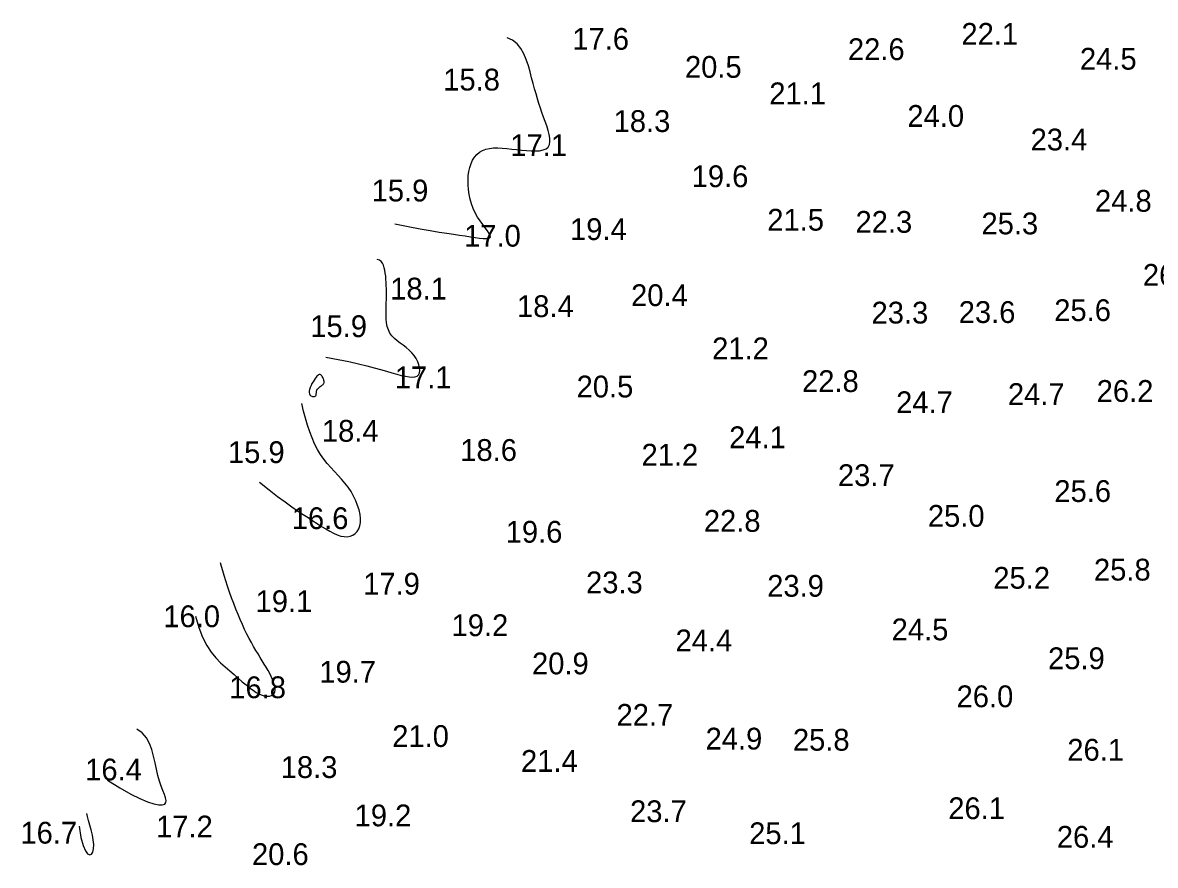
# Model space of a CAD drawing. Extents: x 3040093 to 3056816, y 408076 to 509144.
# Drawn here: x 3044183.2 to 3044443.1, y 433004.5 to 433197.9 of the extents above; entities that cross this region are included whole.
import ezdxf

# ---------------------------------------------------------------- set-up
doc = ezdxf.new("R2010")
doc.units = 0
doc.layers.add('V-CHAN-CONT-EL17', color=7, linetype='Continuous')
doc.layers.add('V-TOPO-SOUN-0610', color=7, linetype='Continuous')

msp = doc.modelspace()

# ---------------------------------------------------------------- linework, layer by layer
at = {"layer": 'V-CHAN-CONT-EL17'}
for points in [[(3044268.59, 433151.73), (3044271.68, 433151.1), (3044274.38, 433150.58), (3044276.72, 433150.17), (3044278.75, 433149.83), (3044280.53, 433149.56), (3044282.09, 433149.33), (3044283.48, 433149.13), (3044284.75, 433148.95), (3044285.94, 433148.77), (3044287.02, 433148.6), (3044288, 433148.46), (3044288.84, 433148.36), (3044289.54, 433148.32), (3044290.07, 433148.36), (3044290.42, 433148.48), (3044290.56, 433148.72), (3044290.5, 433149.08), (3044290.25, 433149.54), (3044289.86, 433150.12), (3044289.37, 433150.79), (3044288.8, 433151.55), (3044288.2, 433152.38), (3044287.61, 433153.29), (3044287.06, 433154.25), (3044286.59, 433155.26), (3044286.19, 433156.31), (3044285.88, 433157.39), (3044285.65, 433158.48), (3044285.49, 433159.58), (3044285.4, 433160.66), (3044285.4, 433161.73), (3044285.46, 433162.76), (3044285.6, 433163.74), (3044285.81, 433164.67), (3044286.1, 433165.54), (3044286.46, 433166.34), (3044286.91, 433167.05), (3044287.43, 433167.66), (3044288.04, 433168.18), (3044288.73, 433168.58), (3044289.5, 433168.86), (3044290.35, 433169.04), (3044291.26, 433169.13), (3044292.24, 433169.15), (3044293.26, 433169.1), (3044294.33, 433169.01), (3044295.43, 433168.89), (3044296.55, 433168.76), (3044297.69, 433168.63), (3044298.81, 433168.52), (3044299.9, 433168.45), (3044300.92, 433168.44), (3044301.84, 433168.51), (3044302.65, 433168.67), (3044303.31, 433168.94), (3044303.79, 433169.35), (3044304.08, 433169.9), (3044304.2, 433170.57), (3044304.17, 433171.36), (3044304.01, 433172.24), (3044303.77, 433173.18), (3044303.45, 433174.18), (3044303.1, 433175.21), (3044302.73, 433176.24), (3044302.37, 433177.27), (3044302.02, 433178.3), (3044301.68, 433179.35), (3044301.34, 433180.42), (3044301.01, 433181.53), (3044300.67, 433182.69), (3044300.34, 433183.92), (3044300, 433185.21), (3044299.64, 433186.59), (3044299.25, 433188), (3044298.78, 433189.4), (3044298.22, 433190.74), (3044297.53, 433191.96), (3044296.67, 433193.02), (3044295.62, 433193.86), (3044294.35, 433194.44)], [(3044252.8, 433121.1), (3044255.61, 433120.6), (3044258.08, 433120.1), (3044260.25, 433119.61), (3044262.17, 433119.15), (3044263.85, 433118.7), (3044265.34, 433118.28), (3044266.68, 433117.89), (3044267.9, 433117.53), (3044269.04, 433117.21), (3044270.08, 433116.94), (3044271.03, 433116.73), (3044271.88, 433116.6), (3044272.61, 433116.55), (3044273.22, 433116.61), (3044273.71, 433116.77), (3044274.06, 433117.07), (3044274.27, 433117.49), (3044274.35, 433118.03), (3044274.3, 433118.65), (3044274.14, 433119.33), (3044273.87, 433120.05), (3044273.49, 433120.78), (3044273.03, 433121.49), (3044272.48, 433122.15), (3044271.86, 433122.76), (3044271.19, 433123.31), (3044270.5, 433123.84), (3044269.8, 433124.35), (3044269.12, 433124.87), (3044268.49, 433125.41), (3044267.94, 433126), (3044267.47, 433126.65), (3044267.12, 433127.38), (3044266.87, 433128.18), (3044266.71, 433129.03), (3044266.62, 433129.91), (3044266.58, 433130.83), (3044266.58, 433131.74), (3044266.61, 433132.66), (3044266.64, 433133.55), (3044266.66, 433134.41), (3044266.67, 433135.24), (3044266.67, 433136.04), (3044266.66, 433136.81), (3044266.64, 433137.56), (3044266.61, 433138.29), (3044266.56, 433139), (3044266.5, 433139.7), (3044266.42, 433140.39), (3044266.32, 433141.05), (3044266.19, 433141.66), (3044266, 433142.22), (3044265.76, 433142.71), (3044265.45, 433143.1), (3044265.05, 433143.39), (3044264.57, 433143.55)], [(3044237.56, 433092.43), (3044239.75, 433090.67), (3044241.7, 433089.17), (3044243.42, 433087.89), (3044244.94, 433086.79), (3044246.3, 433085.85), (3044247.54, 433085.03), (3044248.68, 433084.29), (3044249.75, 433083.59), (3044250.78, 433082.92), (3044251.77, 433082.29), (3044252.73, 433081.69), (3044253.65, 433081.16), (3044254.54, 433080.7), (3044255.38, 433080.34), (3044256.19, 433080.07), (3044256.96, 433079.93), (3044257.68, 433079.92), (3044258.35, 433080.04), (3044258.96, 433080.28), (3044259.5, 433080.64), (3044259.96, 433081.12), (3044260.31, 433081.71), (3044260.57, 433082.4), (3044260.7, 433083.19), (3044260.71, 433084.08), (3044260.61, 433085.04), (3044260.39, 433086.06), (3044260.06, 433087.11), (3044259.64, 433088.18), (3044259.14, 433089.25), (3044258.55, 433090.29), (3044257.88, 433091.29), (3044257.16, 433092.23), (3044256.38, 433093.12), (3044255.57, 433094), (3044254.74, 433094.87), (3044253.91, 433095.77), (3044253.08, 433096.7), (3044252.29, 433097.69), (3044251.54, 433098.77), (3044250.84, 433099.95), (3044250.2, 433101.21), (3044249.61, 433102.57), (3044249.06, 433104.01), (3044248.55, 433105.53), (3044248.08, 433107.11), (3044247.64, 433108.75), (3044247.23, 433110.45)], [(3044222.83, 433061.7), (3044223.6, 433059.06), (3044224.46, 433056.84), (3044225.42, 433054.98), (3044226.44, 433053.43), (3044227.5, 433052.12), (3044228.58, 433051), (3044229.65, 433050.02), (3044230.7, 433049.12), (3044231.71, 433048.26), (3044232.67, 433047.42), (3044233.58, 433046.64), (3044234.46, 433045.91), (3044235.28, 433045.24), (3044236.07, 433044.66), (3044236.81, 433044.17), (3044237.51, 433043.79), (3044238.17, 433043.51), (3044238.79, 433043.34), (3044239.34, 433043.28), (3044239.84, 433043.31), (3044240.26, 433043.44), (3044240.61, 433043.65), (3044240.87, 433043.95), (3044241.04, 433044.32), (3044241.1, 433044.77), (3044241.08, 433045.28), (3044240.97, 433045.85), (3044240.79, 433046.46), (3044240.55, 433047.12), (3044240.24, 433047.8), (3044239.9, 433048.5), (3044239.51, 433049.22), (3044239.09, 433049.94), (3044238.65, 433050.68), (3044238.19, 433051.43), (3044237.71, 433052.2), (3044237.21, 433053), (3044236.7, 433053.83), (3044236.19, 433054.7), (3044235.67, 433055.61), (3044235.16, 433056.57), (3044234.64, 433057.58), (3044234.13, 433058.63), (3044233.62, 433059.73), (3044233.11, 433060.88), (3044232.61, 433062.07), (3044232.11, 433063.3), (3044231.62, 433064.58), (3044231.14, 433065.89), (3044230.67, 433067.22), (3044230.23, 433068.54), (3044229.81, 433069.81), (3044229.43, 433071.01), (3044229.1, 433072.12), (3044228.81, 433073.11), (3044228.59, 433073.94)], [(3044202.66, 433024.01), (3044205.52, 433022.25), (3044207.99, 433020.85), (3044210.1, 433019.8), (3044211.87, 433019.06), (3044213.3, 433018.6), (3044214.42, 433018.38), (3044215.24, 433018.38), (3044215.78, 433018.55), (3044216.06, 433018.88), (3044216.11, 433019.35), (3044215.99, 433019.97), (3044215.73, 433020.73), (3044215.38, 433021.63), (3044214.98, 433022.66), (3044214.56, 433023.83), (3044214.19, 433025.12), (3044213.87, 433026.54), (3044213.57, 433028.03), (3044213.25, 433029.55), (3044212.84, 433031.04), (3044212.31, 433032.46), (3044211.59, 433033.76), (3044210.63, 433034.87), (3044209.38, 433035.76)], [(3044196.12, 433013.45), (3044196.55, 433010.9), (3044197.05, 433009.04), (3044197.57, 433007.79), (3044198.09, 433007.1), (3044198.57, 433006.87), (3044198.99, 433007.05), (3044199.3, 433007.55), (3044199.48, 433008.31), (3044199.51, 433009.24), (3044199.4, 433010.31), (3044199.2, 433011.45), (3044198.93, 433012.61), (3044198.63, 433013.74), (3044198.33, 433014.78), (3044198.07, 433015.68), (3044197.88, 433016.4)]]:
    msp.add_lwpolyline(points, dxfattribs=at)
msp.add_lwpolyline([(3044250.07, 433115.86), (3044249.82, 433115.47), (3044249.59, 433115.04), (3044249.37, 433114.6), (3044249.18, 433114.16), (3044249.04, 433113.73), (3044248.96, 433113.33), (3044248.94, 433112.98), (3044249, 433112.69), (3044249.13, 433112.46), (3044249.31, 433112.28), (3044249.52, 433112.16), (3044249.74, 433112.08), (3044249.96, 433112.06), (3044250.16, 433112.08), (3044250.32, 433112.15), (3044250.44, 433112.25), (3044250.51, 433112.39), (3044250.55, 433112.56), (3044250.57, 433112.75), (3044250.59, 433112.95), (3044250.61, 433113.16), (3044250.65, 433113.37), (3044250.72, 433113.57), (3044250.83, 433113.76), (3044250.97, 433113.93), (3044251.13, 433114.1), (3044251.31, 433114.25), (3044251.5, 433114.39), (3044251.68, 433114.52), (3044251.85, 433114.64), (3044252.01, 433114.76), (3044252.13, 433114.86), (3044252.23, 433114.97), (3044252.3, 433115.08), (3044252.34, 433115.18), (3044252.37, 433115.3), (3044252.37, 433115.43), (3044252.35, 433115.57), (3044252.32, 433115.73), (3044252.27, 433115.9), (3044252.21, 433116.09), (3044252.14, 433116.28), (3044252.05, 433116.47), (3044251.96, 433116.65), (3044251.85, 433116.81), (3044251.74, 433116.95), (3044251.62, 433117.05), (3044251.5, 433117.12), (3044251.36, 433117.14), (3044251.22, 433117.11), (3044251.06, 433117.04), (3044250.9, 433116.92), (3044250.72, 433116.74), (3044250.52, 433116.5), (3044250.3, 433116.21)], close=True, dxfattribs=at)

# ---------------------------------------------------------------- texts
at = {"layer": 'V-TOPO-SOUN-0610'}
for s, p in [('17.6 ', (3044309.34, 433191.67)), ('22.1 ', (3044398.64, 433192.82)), ('22.6 ', (3044372.59, 433189.3)), ('20.5 ', (3044335.19, 433185.24)), ('24.5 ', (3044425.84, 433187.11)), ('15.8 ', (3044279.71, 433182.32)), ('21.1 ', (3044354.55, 433179.17)), ('18.3 ', (3044318.82, 433172.8)), ('24.0 ', (3044386.24, 433173.98)), ('17.1 ', (3044295.1, 433167.26)), ('23.4 ', (3044414.52, 433168.57)), ('19.6 ', (3044336.73, 433160.14)), ('15.9 ', (3044263.28, 433156.86)), ('24.8 ', (3044429.29, 433154.5)), ('21.5 ', (3044354.09, 433150.16)), ('22.3 ', (3044374.33, 433149.67)), ('25.3 ', (3044403.24, 433149.31)), ('17.0 ', (3044284.5, 433146.49)), ('19.4 ', (3044308.81, 433148)), ('26.1 ', (3044440.28, 433137.5)), ('18.1 ', (3044267.54, 433134.35)), ('20.4 ', (3044322.82, 433132.84)), ('18.4 ', (3044296.64, 433130.32)), ('23.3 ', (3044378.01, 433128.84)), ('23.6 ', (3044398.02, 433128.97)), ('25.6 ', (3044419.94, 433129.4)), ('15.9 ', (3044249.2, 433125.72)), ('21.2 ', (3044341.43, 433120.64)), ('17.1 ', (3044268.59, 433113.98)), ('22.8 ', (3044362.06, 433113.12)), ('20.5 ', (3044310.32, 433111.88)), ('24.7 ', (3044409.31, 433110.14)), ('26.2 ', (3044429.68, 433110.86)), ('24.7 ', (3044383.65, 433108.27)), ('18.4 ', (3044251.86, 433101.71)), ('24.1 ', (3044345.33, 433100.23)), ('15.9 ', (3044230.3, 433096.82)), ('18.6 ', (3044283.62, 433097.31)), ('21.2 ', (3044325.22, 433096.23)), ('23.7 ', (3044370.3, 433091.54)), ('25.6 ', (3044419.97, 433087.89)), ('16.6 ', (3044244.94, 433081.66)), ('25.0 ', (3044390.93, 433082.19)), ('22.8 ', (3044339.52, 433081.04)), ('19.6 ', (3044294.05, 433078.54)), ('25.8 ', (3044429.06, 433069.85)), ('17.9 ', (3044261.34, 433066.63)), ('23.3 ', (3044312.49, 433066.93)), ('23.9 ', (3044354.06, 433066.14)), ('25.2 ', (3044405.96, 433067.98)), ('19.1 ', (3044236.64, 433062.6)), ('16.0 ', (3044215.47, 433059.15)), ('19.2 ', (3044281.62, 433057.09)), ('24.5 ', (3044382.63, 433056.14)), ('24.4 ', (3044333.03, 433053.61)), ('20.9 ', (3044300.09, 433048.33)), ('25.9 ', (3044418.52, 433049.51)), ('19.7 ', (3044251.27, 433046.42)), ('16.8 ', (3044230.6, 433042.85)), ('26.0 ', (3044397.53, 433040.78)), ('22.7 ', (3044319.48, 433036.52)), ('21.0 ', (3044268, 433031.66)), ('24.9 ', (3044339.92, 433031.07)), ('25.8 ', (3044359.96, 433030.81)), ('26.1 ', (3044422.95, 433028.51)), ('16.4 ', (3044197.53, 433023.98)), ('18.3 ', (3044242.41, 433024.54)), ('21.4 ', (3044297.56, 433025.95)), ('23.7 ', (3044322.59, 433014.4)), ('26.1 ', (3044395.62, 433015.09)), ('19.2 ', (3044259.37, 433013.45)), ('16.7 ', (3044182.67, 433009.48)), ('17.2 ', (3044213.8, 433010.89)), ('25.1 ', (3044349.92, 433009.35)), ('26.4 ', (3044420.53, 433008.53)), ('20.6 ', (3044235.82, 433004.56))]:
    msp.add_text(s, height=5, dxfattribs=at).set_placement(p)

doc.saveas('drawing.dxf')
